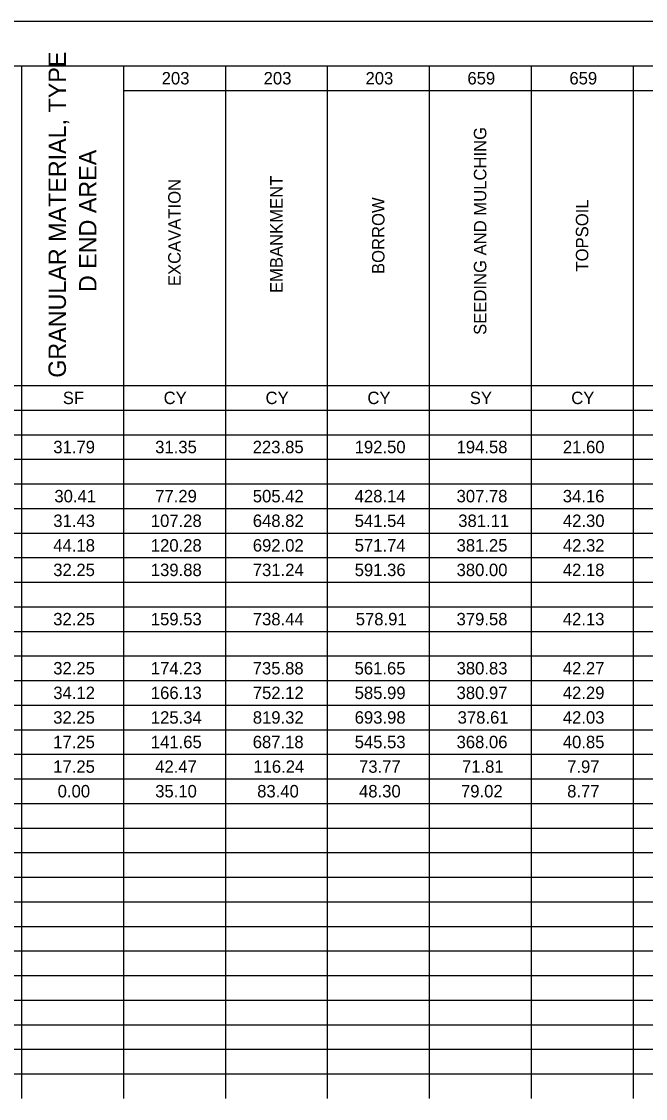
# Model space of a CAD drawing. Extents: x 0 to 34, y 0 to 22.
# Drawn here: x 12.08 to 19.1, y 9.88 to 22 of the extents above; entities that cross this region are included whole.
import ezdxf

# ---------------------------------------------------------------- set-up
doc = ezdxf.new("R2010")
doc.units = 0
for name, color, linetype in [('Default', 7, 'Continuous'), ('SH_Border', 7, 'Continuous'), ('SH_Cut_Line', 7, 'Continuous')]:
    doc.layers.add(name, color=color, linetype=linetype)

msp = doc.modelspace()

# ---------------------------------------------------------------- linework, layer by layer
at = {"layer": 'Default'}
for p, q in [((8.642, 21.5), (12.081, 21.5)), ((12.081, 21.5), (13.227, 21.5)), ((12.081, 21.5), (12.081, 21.223)), ((13.227, 21.5), (14.373, 21.5)), ((13.227, 21.5), (13.227, 21.223)), ((14.373, 21.5), (15.52, 21.5)), ((14.373, 21.5), (14.373, 21.223)), ((15.52, 21.5), (25.837, 21.5)), ((15.52, 21.5), (15.52, 21.223)), ((16.666, 21.5), (16.666, 21.223)), ((17.812, 21.5), (17.812, 21.223)), ((18.959, 21.5), (18.959, 21.223)), ((12.081, 21.223), (12.081, 20.947)), ((13.227, 21.223), (14.373, 21.223)), ((13.227, 21.223), (13.227, 20.947)), ((14.373, 21.223), (15.52, 21.223)), ((14.373, 21.223), (14.373, 20.947)), ((15.52, 21.223), (25.837, 21.223)), ((15.52, 21.223), (15.52, 20.947)), ((16.666, 21.223), (16.666, 20.947)), ((17.812, 21.223), (17.812, 20.947)), ((18.959, 21.223), (18.959, 20.947)), ((12.081, 20.947), (12.081, 20.67)), ((13.227, 20.947), (13.227, 20.67)), ((14.373, 20.947), (14.373, 20.67)), ((15.52, 20.947), (15.52, 20.67)), ((16.666, 20.947), (16.666, 20.67)), ((17.812, 20.947), (17.812, 20.67)), ((18.959, 20.947), (18.959, 20.67)), ((12.081, 20.67), (12.081, 20.116)), ((13.227, 20.67), (13.227, 20.116)), ((14.373, 20.67), (14.373, 20.116)), ((15.52, 20.67), (15.52, 20.116)), ((16.666, 20.67), (16.666, 20.116)), ((17.812, 20.67), (17.812, 20.116)), ((18.959, 20.67), (18.959, 20.116)), ((12.081, 20.116), (12.081, 19.84)), ((13.227, 20.116), (13.227, 19.84)), ((14.373, 20.116), (14.373, 19.84)), ((15.52, 20.116), (15.52, 19.84)), ((16.666, 20.116), (16.666, 19.84)), ((17.812, 20.116), (17.812, 19.84)), ((18.959, 20.116), (18.959, 19.84)), ((12.081, 19.84), (12.081, 19.563)), ((13.227, 19.84), (13.227, 19.563)), ((14.373, 19.84), (14.373, 19.563)), ((15.52, 19.84), (15.52, 19.563)), ((16.666, 19.84), (16.666, 19.563)), ((17.812, 19.84), (17.812, 19.563)), ((18.959, 19.84), (18.959, 19.563)), ((12.081, 19.563), (12.081, 19.286)), ((13.227, 19.563), (13.227, 19.286)), ((14.373, 19.563), (14.373, 19.286)), ((15.52, 19.563), (15.52, 19.286)), ((16.666, 19.563), (16.666, 19.286)), ((17.812, 19.563), (17.812, 19.286)), ((18.959, 19.563), (18.959, 19.286)), ((12.081, 19.286), (12.081, 19.01)), ((13.227, 19.286), (13.227, 19.01)), ((14.373, 19.286), (14.373, 19.01)), ((15.52, 19.286), (15.52, 19.01)), ((16.666, 19.286), (16.666, 19.01)), ((17.812, 19.286), (17.812, 19.01)), ((18.959, 19.286), (18.959, 19.01)), ((12.081, 19.01), (12.081, 18.733)), ((13.227, 19.01), (13.227, 18.733)), ((14.373, 19.01), (14.373, 18.733)), ((15.52, 19.01), (15.52, 18.733)), ((16.666, 19.01), (16.666, 18.733)), ((17.812, 19.01), (17.812, 18.733)), ((18.959, 19.01), (18.959, 18.733)), ((12.081, 18.733), (12.081, 18.456)), ((13.227, 18.733), (13.227, 18.456)), ((14.373, 18.733), (14.373, 18.456)), ((15.52, 18.733), (15.52, 18.456)), ((16.666, 18.733), (16.666, 18.456)), ((17.812, 18.733), (17.812, 18.456)), ((18.959, 18.733), (18.959, 18.456)), ((12.081, 18.456), (12.081, 18.18)), ((13.227, 18.456), (13.227, 18.18)), ((14.373, 18.456), (14.373, 18.18)), ((15.52, 18.456), (15.52, 18.18)), ((16.666, 18.456), (16.666, 18.18)), ((17.812, 18.456), (17.812, 18.18)), ((18.959, 18.456), (18.959, 18.18)), ((12.081, 18.18), (12.081, 17.903)), ((13.227, 18.18), (13.227, 17.903)), ((14.373, 18.18), (14.373, 17.903)), ((15.52, 18.18), (15.52, 17.903)), ((16.666, 18.18), (16.666, 17.903)), ((17.812, 18.18), (17.812, 17.903)), ((18.959, 18.18), (18.959, 17.903)), ((8.642, 17.903), (12.081, 17.903)), ((12.081, 17.903), (13.227, 17.903)), ((12.081, 17.903), (12.081, 17.626)), ((13.227, 17.903), (14.373, 17.903)), ((13.227, 17.903), (13.227, 17.626)), ((14.373, 17.903), (15.52, 17.903)), ((14.373, 17.903), (14.373, 17.626)), ((15.52, 17.903), (25.837, 17.903)), ((15.52, 17.903), (15.52, 17.626)), ((16.666, 17.903), (16.666, 17.626)), ((17.812, 17.903), (17.812, 17.626)), ((18.959, 17.903), (18.959, 17.626)), ((8.642, 17.626), (12.081, 17.626)), ((12.081, 17.626), (13.227, 17.626)), ((12.081, 17.626), (12.081, 17.349)), ((13.227, 17.626), (14.373, 17.626)), ((13.227, 17.626), (13.227, 17.349)), ((14.373, 17.626), (15.52, 17.626)), ((14.373, 17.626), (14.373, 17.349)), ((15.52, 17.626), (25.837, 17.626)), ((15.52, 17.626), (15.52, 17.349)), ((16.666, 17.626), (16.666, 17.349)), ((17.812, 17.626), (17.812, 17.349)), ((18.959, 17.626), (18.959, 17.349)), ((8.642, 17.349), (12.081, 17.349)), ((12.081, 17.349), (13.227, 17.349)), ((12.081, 17.349), (12.081, 17.073)), ((13.227, 17.349), (14.373, 17.349)), ((13.227, 17.349), (13.227, 17.073)), ((14.373, 17.349), (15.52, 17.349)), ((14.373, 17.349), (14.373, 17.073)), ((15.52, 17.349), (25.837, 17.349)), ((15.52, 17.349), (15.52, 17.073)), ((16.666, 17.349), (16.666, 17.073)), ((17.812, 17.349), (17.812, 17.073)), ((18.959, 17.349), (18.959, 17.073)), ((8.642, 17.073), (12.081, 17.073)), ((12.081, 17.073), (13.227, 17.073)), ((12.081, 17.073), (12.081, 16.796)), ((13.227, 17.073), (14.373, 17.073)), ((13.227, 17.073), (13.227, 16.796)), ((14.373, 17.073), (15.52, 17.073)), ((14.373, 17.073), (14.373, 16.796)), ((15.52, 17.073), (25.837, 17.073)), ((15.52, 17.073), (15.52, 16.796)), ((16.666, 17.073), (16.666, 16.796)), ((17.812, 17.073), (17.812, 16.796)), ((18.959, 17.073), (18.959, 16.796)), ((8.642, 16.796), (12.081, 16.796)), ((12.081, 16.796), (13.227, 16.796)), ((12.081, 16.796), (12.081, 16.243)), ((13.227, 16.796), (14.373, 16.796)), ((13.227, 16.796), (13.227, 16.243)), ((14.373, 16.796), (15.52, 16.796)), ((14.373, 16.796), (14.373, 16.243)), ((15.52, 16.796), (25.837, 16.796)), ((15.52, 16.796), (15.52, 16.243)), ((16.666, 16.796), (16.666, 16.243)), ((17.812, 16.796), (17.812, 16.243)), ((18.959, 16.796), (18.959, 16.243)), ((8.642, 16.519), (12.081, 16.519)), ((12.081, 16.519), (13.227, 16.519)), ((13.227, 16.519), (14.373, 16.519)), ((14.373, 16.519), (15.52, 16.519)), ((15.52, 16.519), (25.837, 16.519)), ((8.642, 16.243), (12.081, 16.243)), ((12.081, 16.243), (13.227, 16.243)), ((12.081, 16.243), (12.081, 15.966)), ((13.227, 16.243), (14.373, 16.243)), ((13.227, 16.243), (13.227, 15.966)), ((14.373, 16.243), (15.52, 16.243)), ((14.373, 16.243), (14.373, 15.966)), ((15.52, 16.243), (25.837, 16.243)), ((15.52, 16.243), (15.52, 15.966)), ((16.666, 16.243), (16.666, 15.966)), ((17.812, 16.243), (17.812, 15.966)), ((18.959, 16.243), (18.959, 15.966)), ((8.642, 15.966), (12.081, 15.966)), ((12.081, 15.966), (13.227, 15.966)), ((12.081, 15.966), (12.081, 15.689)), ((13.227, 15.966), (14.373, 15.966)), ((13.227, 15.966), (13.227, 15.689)), ((14.373, 15.966), (15.52, 15.966)), ((14.373, 15.966), (14.373, 15.689)), ((15.52, 15.966), (25.837, 15.966)), ((15.52, 15.966), (15.52, 15.689)), ((16.666, 15.966), (16.666, 15.689)), ((17.812, 15.966), (17.812, 15.689)), ((18.959, 15.966), (18.959, 15.689)), ((8.642, 15.689), (12.081, 15.689)), ((12.081, 15.689), (13.227, 15.689)), ((12.081, 15.689), (12.081, 15.412)), ((13.227, 15.689), (14.373, 15.689)), ((13.227, 15.689), (13.227, 15.412)), ((14.373, 15.689), (15.52, 15.689)), ((14.373, 15.689), (14.373, 15.412)), ((15.52, 15.689), (25.837, 15.689)), ((15.52, 15.689), (15.52, 15.412)), ((16.666, 15.689), (16.666, 15.412)), ((17.812, 15.689), (17.812, 15.412)), ((18.959, 15.689), (18.959, 15.412)), ((8.642, 15.412), (12.081, 15.412)), ((12.081, 15.412), (13.227, 15.412)), ((12.081, 15.412), (12.081, 14.859)), ((13.227, 15.412), (14.373, 15.412)), ((13.227, 15.412), (13.227, 14.859)), ((14.373, 15.412), (15.52, 15.412)), ((14.373, 15.412), (14.373, 14.859)), ((15.52, 15.412), (25.837, 15.412)), ((15.52, 15.412), (15.52, 14.859)), ((16.666, 15.412), (16.666, 14.859)), ((17.812, 15.412), (17.812, 14.859)), ((18.959, 15.412), (18.959, 14.859)), ((8.642, 15.136), (12.081, 15.136)), ((12.081, 15.136), (13.227, 15.136)), ((13.227, 15.136), (14.373, 15.136)), ((14.373, 15.136), (15.52, 15.136)), ((15.52, 15.136), (25.837, 15.136)), ((8.642, 14.859), (12.081, 14.859)), ((12.081, 14.859), (13.227, 14.859)), ((12.081, 14.859), (12.081, 14.582)), ((13.227, 14.859), (14.373, 14.859)), ((13.227, 14.859), (13.227, 14.582)), ((14.373, 14.859), (15.52, 14.859)), ((14.373, 14.859), (14.373, 14.582)), ((15.52, 14.859), (25.837, 14.859)), ((15.52, 14.859), (15.52, 14.582)), ((16.666, 14.859), (16.666, 14.582)), ((17.812, 14.859), (17.812, 14.582)), ((18.959, 14.859), (18.959, 14.582)), ((8.642, 14.582), (12.081, 14.582)), ((12.081, 14.582), (13.227, 14.582)), ((12.081, 14.582), (12.081, 14.306)), ((13.227, 14.582), (14.373, 14.582)), ((13.227, 14.582), (13.227, 14.306)), ((14.373, 14.582), (15.52, 14.582)), ((14.373, 14.582), (14.373, 14.306)), ((15.52, 14.582), (25.837, 14.582)), ((15.52, 14.582), (15.52, 14.306)), ((16.666, 14.582), (16.666, 14.306)), ((17.812, 14.582), (17.812, 14.306)), ((18.959, 14.582), (18.959, 14.306)), ((8.642, 14.306), (12.081, 14.306)), ((12.081, 14.306), (13.227, 14.306)), ((12.081, 14.306), (12.081, 14.029)), ((13.227, 14.306), (14.373, 14.306)), ((13.227, 14.306), (13.227, 14.029)), ((14.373, 14.306), (15.52, 14.306)), ((14.373, 14.306), (14.373, 14.029)), ((15.52, 14.306), (25.837, 14.306)), ((15.52, 14.306), (15.52, 14.029)), ((16.666, 14.306), (16.666, 14.029)), ((17.812, 14.306), (17.812, 14.029)), ((18.959, 14.306), (18.959, 14.029)), ((8.642, 14.029), (12.081, 14.029)), ((12.081, 14.029), (13.227, 14.029)), ((12.081, 14.029), (12.081, 13.199)), ((13.227, 14.029), (14.373, 14.029)), ((13.227, 14.029), (13.227, 13.199)), ((14.373, 14.029), (15.52, 14.029)), ((14.373, 14.029), (14.373, 13.199)), ((15.52, 14.029), (25.837, 14.029)), ((15.52, 14.029), (15.52, 13.199)), ((16.666, 14.029), (16.666, 13.199)), ((17.812, 14.029), (17.812, 13.199)), ((18.959, 14.029), (18.959, 13.199)), ((8.642, 13.752), (12.081, 13.752)), ((12.081, 13.752), (13.227, 13.752)), ((13.227, 13.752), (14.373, 13.752)), ((14.373, 13.752), (15.52, 13.752)), ((15.52, 13.752), (25.837, 13.752)), ((8.642, 13.476), (12.081, 13.476)), ((12.081, 13.476), (13.227, 13.476)), ((13.227, 13.476), (14.373, 13.476)), ((14.373, 13.476), (15.52, 13.476)), ((15.52, 13.476), (25.837, 13.476)), ((8.642, 13.199), (12.081, 13.199)), ((12.081, 13.199), (13.227, 13.199)), ((12.081, 13.199), (12.081, 12.922)), ((13.227, 13.199), (14.373, 13.199)), ((13.227, 13.199), (13.227, 12.922)), ((14.373, 13.199), (15.52, 13.199)), ((14.373, 13.199), (14.373, 12.922)), ((15.52, 13.199), (25.837, 13.199)), ((15.52, 13.199), (15.52, 12.922)), ((16.666, 13.199), (16.666, 12.922)), ((17.812, 13.199), (17.812, 12.922)), ((18.959, 13.199), (18.959, 12.922)), ((8.642, 12.922), (12.081, 12.922)), ((12.081, 12.922), (13.227, 12.922)), ((12.081, 12.922), (12.081, 11.815)), ((13.227, 12.922), (14.373, 12.922)), ((13.227, 12.922), (13.227, 11.815)), ((14.373, 12.922), (15.52, 12.922)), ((14.373, 12.922), (14.373, 11.815)), ((15.52, 12.922), (25.837, 12.922)), ((15.52, 12.922), (15.52, 11.815)), ((16.666, 12.922), (16.666, 11.815)), ((17.812, 12.922), (17.812, 11.815)), ((18.959, 12.922), (18.959, 11.815)), ((8.642, 12.645), (12.081, 12.645)), ((12.081, 12.645), (13.227, 12.645)), ((13.227, 12.645), (14.373, 12.645)), ((14.373, 12.645), (15.52, 12.645)), ((15.52, 12.645), (25.837, 12.645)), ((8.642, 12.369), (12.081, 12.369)), ((12.081, 12.369), (13.227, 12.369)), ((13.227, 12.369), (14.373, 12.369)), ((14.373, 12.369), (15.52, 12.369)), ((15.52, 12.369), (25.837, 12.369)), ((8.642, 12.092), (12.081, 12.092)), ((12.081, 12.092), (13.227, 12.092)), ((13.227, 12.092), (14.373, 12.092)), ((14.373, 12.092), (15.52, 12.092)), ((15.52, 12.092), (25.837, 12.092)), ((8.642, 11.815), (12.081, 11.815)), ((12.081, 11.815), (13.227, 11.815)), ((12.081, 11.815), (12.081, 11.539)), ((13.227, 11.815), (14.373, 11.815)), ((13.227, 11.815), (13.227, 11.539)), ((14.373, 11.815), (15.52, 11.815)), ((14.373, 11.815), (14.373, 11.539)), ((15.52, 11.815), (25.837, 11.815)), ((15.52, 11.815), (15.52, 11.539)), ((16.666, 11.815), (16.666, 11.539)), ((17.812, 11.815), (17.812, 11.539)), ((18.959, 11.815), (18.959, 11.539)), ((8.642, 11.539), (12.081, 11.539)), ((12.081, 11.539), (13.227, 11.539)), ((12.081, 11.539), (12.081, 10.432)), ((13.227, 11.539), (14.373, 11.539)), ((13.227, 11.539), (13.227, 10.432)), ((14.373, 11.539), (15.52, 11.539)), ((14.373, 11.539), (14.373, 10.432)), ((15.52, 11.539), (25.837, 11.539)), ((15.52, 11.539), (15.52, 10.432)), ((16.666, 11.539), (16.666, 10.432)), ((17.812, 11.539), (17.812, 10.432)), ((18.959, 11.539), (18.959, 10.432)), ((8.642, 11.262), (12.081, 11.262)), ((12.081, 11.262), (13.227, 11.262)), ((13.227, 11.262), (14.373, 11.262)), ((14.373, 11.262), (15.52, 11.262)), ((15.52, 11.262), (25.837, 11.262)), ((8.642, 10.985), (12.081, 10.985)), ((12.081, 10.985), (13.227, 10.985)), ((13.227, 10.985), (14.373, 10.985)), ((14.373, 10.985), (15.52, 10.985)), ((15.52, 10.985), (25.837, 10.985)), ((8.642, 10.708), (12.081, 10.708)), ((12.081, 10.708), (13.227, 10.708)), ((13.227, 10.708), (14.373, 10.708)), ((14.373, 10.708), (15.52, 10.708)), ((15.52, 10.708), (25.837, 10.708)), ((8.642, 10.432), (12.081, 10.432)), ((12.081, 10.432), (13.227, 10.432)), ((12.081, 10.432), (12.081, 9.878)), ((13.227, 10.432), (14.373, 10.432)), ((13.227, 10.432), (13.227, 9.878)), ((14.373, 10.432), (15.52, 10.432)), ((14.373, 10.432), (14.373, 9.878)), ((15.52, 10.432), (25.837, 10.432)), ((15.52, 10.432), (15.52, 9.878)), ((16.666, 10.432), (16.666, 9.878)), ((17.812, 10.432), (17.812, 9.878)), ((18.959, 10.432), (18.959, 9.878)), ((8.642, 10.155), (12.081, 10.155)), ((12.081, 10.155), (13.227, 10.155)), ((13.227, 10.155), (14.373, 10.155)), ((14.373, 10.155), (15.52, 10.155)), ((15.52, 10.155), (25.837, 10.155))]:
    msp.add_line(p, q, dxfattribs=at)
at = {"layer": 'SH_Border'}
msp.add_lwpolyline([(1.5, 21.5), (33.5, 21.5), (33.5, 0.5), (1.5, 0.5)], close=True, dxfattribs=at)
at = {"layer": 'SH_Cut_Line'}
msp.add_lwpolyline([(0, 0), (34, 0), (34, 22), (0, 22)], close=True, dxfattribs=at)

# ---------------------------------------------------------------- texts
at = {"layer": 'Default'}
for s, height, p in [('GRANULAR MATERIAL, TYPE ', 0.196, (12.58, 17.991)), ('SEEDING AND MULCHING', 0.14, (17.309, 18.473)), ('D END AREA', 0.196, (12.923, 18.955)), ('EMBANKMENT', 0.14, (15.017, 18.944)), ('EXCAVATION', 0.14, (13.87, 19.022)), ('BORROW', 0.14, (16.163, 19.158)), ('TOPSOIL', 0.14, (18.456, 19.186))]:
    msp.add_text(s, height=height, rotation=90, dxfattribs=at).set_placement(p)
for s, p in [('203', (13.657, 21.292)), ('203', (14.804, 21.292)), ('203', (15.95, 21.292)), ('659', (17.096, 21.292)), ('659', (18.243, 21.292)), ('SF', (12.545, 17.694)), ('CY', (13.679, 17.694)), ('CY', (14.825, 17.694)), ('CY', (15.971, 17.694)), ('SY', (17.123, 17.694)), ('CY', (18.264, 17.694)), ('31.79', (12.438, 17.141)), ('31.35', (13.584, 17.141)), ('223.85', (14.681, 17.141)), ('192.50', (15.828, 17.141)), ('194.58', (16.974, 17.141)), ('21.60', (18.17, 17.141)), ('30.41', (12.45, 16.588)), ('77.29', (13.584, 16.588)), ('505.42', (14.682, 16.588)), ('428.14', (15.828, 16.588)), ('307.78', (16.974, 16.588)), ('34.16', (18.169, 16.588)), ('31.43', (12.438, 16.311)), ('107.28', (13.535, 16.311)), ('648.82', (14.682, 16.311)), ('541.54', (15.828, 16.311)), ('381.11', (16.993, 16.311)), ('42.30', (18.17, 16.311)), ('44.18', (12.438, 16.034)), ('120.28', (13.535, 16.034)), ('692.02', (14.682, 16.034)), ('571.74', (15.828, 16.034)), ('381.25', (16.974, 16.034)), ('42.32', (18.17, 16.034)), ('32.25', (12.437, 15.758)), ('139.88', (13.535, 15.758)), ('731.24', (14.682, 15.758)), ('591.36', (15.828, 15.758)), ('380.00', (16.974, 15.758)), ('42.18', (18.169, 15.758)), ('32.25', (12.437, 15.204)), ('159.53', (13.535, 15.204)), ('738.44', (14.682, 15.204)), ('578.91', (15.84, 15.204)), ('379.58', (16.974, 15.204)), ('42.13', (18.169, 15.204)), ('32.25', (12.437, 14.651)), ('174.23', (13.535, 14.651)), ('735.88', (14.681, 14.651)), ('561.65', (15.827, 14.651)), ('380.83', (16.974, 14.651)), ('42.27', (18.169, 14.651)), ('34.12', (12.438, 14.374)), ('166.13', (13.535, 14.374)), ('752.12', (14.682, 14.374)), ('585.99', (15.828, 14.374)), ('380.97', (16.974, 14.374)), ('42.29', (18.169, 14.374)), ('32.25', (12.437, 14.097)), ('125.34', (13.535, 14.097)), ('819.32', (14.682, 14.097)), ('693.98', (15.828, 14.097)), ('378.61', (16.986, 14.097)), ('42.03', (18.169, 14.097)), ('17.25', (12.437, 13.821)), ('141.65', (13.535, 13.821)), ('687.18', (14.681, 13.821)), ('545.53', (15.828, 13.821)), ('368.06', (16.974, 13.821)), ('40.85', (18.169, 13.821)), ('17.25', (12.437, 13.544)), ('42.47', (13.584, 13.544)), ('116.24', (14.688, 13.544)), ('73.77', (15.877, 13.544)), ('71.81', (17.035, 13.544)), ('7.97', (18.218, 13.544)), ('0.00', (12.487, 13.267)), ('35.10', (13.584, 13.267)), ('83.40', (14.731, 13.267)), ('48.30', (15.877, 13.267)), ('79.02', (17.024, 13.267)), ('8.77', (18.218, 13.267))]:
    msp.add_text(s, height=0.14, dxfattribs=at).set_placement(p)

doc.saveas('drawing.dxf')
